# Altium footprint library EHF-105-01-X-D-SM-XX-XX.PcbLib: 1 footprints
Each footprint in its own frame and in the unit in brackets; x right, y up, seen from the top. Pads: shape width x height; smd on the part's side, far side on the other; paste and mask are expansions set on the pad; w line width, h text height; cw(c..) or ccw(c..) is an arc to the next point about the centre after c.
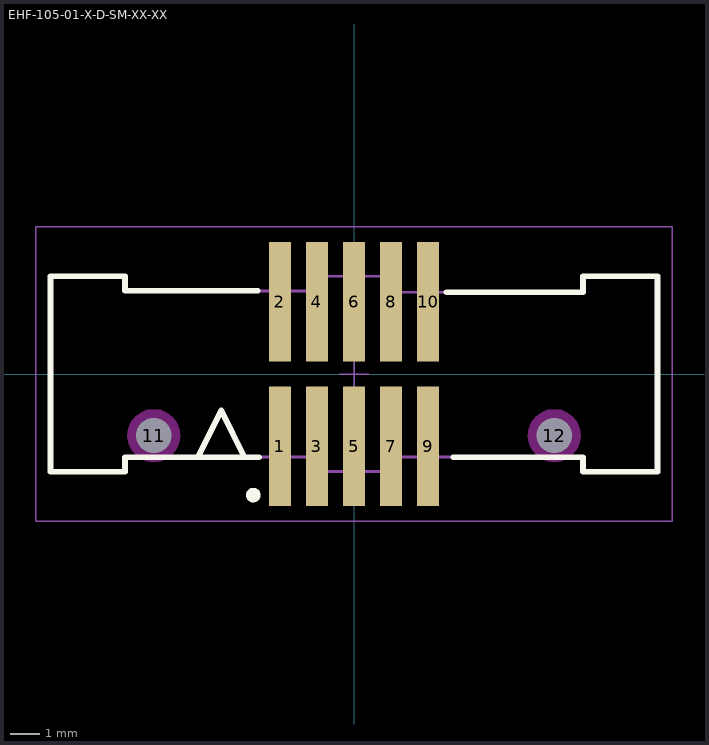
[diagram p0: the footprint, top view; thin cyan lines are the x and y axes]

## EHF-105-01-X-D-SM-XX-XX [mm] "1.27mm pitch, 10 pin, ejector header"
height 8.51
pads (12):
  rect 0.75x4.1 smd mask+0: 1(-2.54,-2.475) 2(-2.54,2.475) 3(-1.27,-2.475) 4(-1.27,2.475) 5(0,-2.475) 6(0,2.475) 7(1.27,-2.475) 8(1.27,2.475) 9(2.54,-2.475) 10(2.54,2.475)
  round 1 hole 1.2 unplated mask+0: 11(-6.86,-2.11) 12(6.86,-2.11)
Top Overlay:
  circle w0.25: c-3.45,-4.15 r0.125
  lines w0.2: -5.35,-2.85 -4.55,-1.25 -3.75,-2.85 ; -3.3,2.85 -7.85,2.85 -7.85,3.35 -10.4,3.35 -10.4,-3.35 -7.85,-3.35 -7.85,-2.85 -3.25,-2.85 ; 3.173,2.8 7.85,2.8 7.85,3.35 10.4,3.35 10.4,-3.35 7.85,-3.35 7.85,-2.85 3.4,-2.85
Keep-Out Layer:
  pour cut-out: -5.952,-2.11 -5.983,-1.875 -6.074,-1.656 -6.218,-1.468 -6.406,-1.324 -6.625,-1.233 -6.86,-1.202 -7.095,-1.233 -7.314,-1.324 -7.502,-1.468 -7.646,-1.656 -7.737,-1.875 -7.768,-2.11 -7.737,-2.345 -7.646,-2.564 -7.502,-2.752 -7.314,-2.896 -7.095,-2.987 -6.86,-3.018 -6.625,-2.987 -6.406,-2.896 -6.218,-2.752 -6.074,-2.564 -5.983,-2.345
  pour cut-out: 7.768,-2.11 7.737,-1.875 7.646,-1.656 7.502,-1.468 7.314,-1.324 7.095,-1.233 6.86,-1.202 6.625,-1.233 6.406,-1.324 6.218,-1.468 6.074,-1.656 5.983,-1.875 5.952,-2.11 5.983,-2.345 6.074,-2.564 6.218,-2.752 6.406,-2.896 6.625,-2.987 6.86,-3.018 7.095,-2.987 7.314,-2.896 7.502,-2.752 7.646,-2.564 7.737,-2.345
Mechanical 12:
  lines w0.001: -10.4,-3.35 -7.85,-3.35 -7.85,-2.85 -1.27,-2.85 -1.27,-3.335 1.27,-3.335 1.27,-2.85 7.85,-2.85 7.85,-3.35 10.4,-3.35 10.4,3.35 7.85,3.35 7.85,2.8 1.25,2.8 1.25,3.35 -1.25,3.35 -1.25,2.85 -7.85,2.85 -7.85,3.35 -10.4,3.35 -10.4,-3.35
Mechanical 13:
  lines w0.1: -5.35,-2.85 -4.55,-1.25 -3.75,-2.85 ; -10.4,-3.35 -7.85,-3.35 -7.85,-2.85 -1.27,-2.85 -1.27,-3.335 1.27,-3.335 1.27,-2.85 7.85,-2.85 7.85,-3.35 10.4,-3.35 10.4,3.35 7.85,3.35 7.85,2.8 1.25,2.8 1.25,3.35 -1.25,3.35 -1.25,2.85 -7.85,2.85 -7.85,3.35 -10.4,3.35 -10.4,-3.35
  text ".Designator" at 0.127,0.254 h1.52
Mechanical 15:
  lines w0.05: -0.5,0 0.5,0 ; 0,-0.5 0,0.5 ; -10.9,-5.05 10.9,-5.05 10.9,5.05 -10.9,5.05 -10.9,-5.05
